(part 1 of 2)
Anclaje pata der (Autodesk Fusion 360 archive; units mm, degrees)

design "Anclaje pata der" references "pilares_anillos_baimax", "Anillos_cuerpo_baimax"
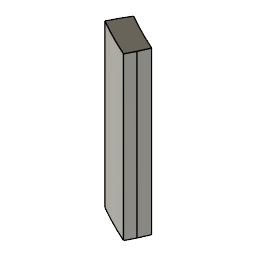
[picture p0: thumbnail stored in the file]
part number: 2026-07-14-14-53-27-253
component_insert "Inserción de componente1"
component_insert "Inserción de componente2"
position "Posición1"
component_insert "Inserción de componente3"
component_insert "Inserción de componente4"
component_insert "Inserción de componente5"
position "Posición2"
sketch "Boceto1" plane through (0, 0, 91.5) normal (0, 0, 1) x axis (1, 0, 0)
  line L1 (1.5, 3) -> (0, 3)
  line L2 (1.5, 0) -> (1.5, 3)
  line L3 (-1.5, 0) -> (1.5, 0)
  line L4 (-1.5, 3) -> (-1.5, 0)
  line L5 (0, 3) -> (-1.5, 3)
  circle C1 centre (0, 1.5) radius 21
  circle C2 centre (0, 1.5) radius 22.75
  circle C3 centre (0, 1.5) radius 5
  point P2 (0, 1.5)
  point P4 (0, 3)
  point P5 (1.5, 3)
  point P6 (1.5, 0)
  point P7 (-1.5, 0)
  point P8 (-1.5, 3)
  concentric C1 C3
  perpendicular L1 L2
  perpendicular L2 L3
  perpendicular L3 L4
  dimension "d1" diameter C3 = 10
  dimension "d2" distance P2 P4 = 1.5
  dimension "d3" distance P4 P5 = 1.5
  dimension "d4" distance P5 P6 = 3
  dimension "d5" distance P6 P7 = 3
  dimension "d6" distance P7 P8 = 3
extrude "Extruir1" new body sketch "Boceto1" profile of L1 L2 L3 L4 L5 along normal blind 7
position "Posición3"
work_plane "PlanoDeObra1" Distance 0
work_plane "PlanoDeObra2" Distance 0
work_plane "PlanoDeObra3" Distance 0
work_plane "PlanoDeObra4" Distance 0
work_plane "PlanoDeObra5" Distance 0
sketch "Boceto2" plane through (-13.1366, 0, 8.8009) normal (-0.8308, 0, 0.5566) x axis (0.5566, 0, 0.8308)
  curve K1 (76.8647, 1.5) -> (74.8126, 1.5)
  curve K2 (75.8387, 7.5) -> (75.8387, -4.5)
  closed curve K3 centre (75.8387, 1.5)
  point P3 (74.8126, 1.5)
  point P4 (76.8647, 1.5)
  point P5 (75.8387, -4.5)
  point P6 (75.8387, 7.5)
  coincident K3 P3
  coincident K3 P4
  coincident K3 P5
  coincident K3 P6
  dimension "d16" = 12
sketch "Boceto3" plane through (-12.068, 0, 51.9927) normal (-0.2261, 0, 0.9741) x axis (0.9741, 0, 0.2261)
  line L1 (52.6699, 3) -> (52.5037, 3)
  line L2 (52.6699, 0) -> (52.5037, 0)
  line L3 (52.6699, 3) -> (52.6699, 0)
  line L4 (53.6699, 1.5) -> (52.6699, 1.5)
  curve K1 (59.1661, 7.4335) -> (59.1661, -4.4335)
  closed curve K2 centre (59.1661, 1.5)
  point P5 (52.6699, 0)
  point P6 (52.6699, 0)
  point P3 (52.6699, 3)
  point P7 (52.6699, 3)
  point P8 (52.6699, 1.5)
  point P11 (59.1661, -4.4335)
  point P12 (59.1661, 7.4335)
  point P9 (53.6699, 1.5)
  coincident P5 P6
  coincident P3 P7
  midpoint L3 P8
  perpendicular L3 L4
  coincident K2 P11
  coincident K2 P12
  dimension "d17" distance P8 P9 = 1
work_plane "PlanoDeObra7" Distance 0
sketch "Boceto4" plane through (37.3705, 0, 0) normal (-1, 0, 0) x axis (0, -1, 0)
  curve K1 (-7.5, 70.5259) -> (4.5, 70.5259)
  curve K2 (-1.5, 67.3726) -> (-1.5, 73.6792)
  closed curve K3 centre (-1.5, 70.5259)
  point P3 (4.5, 70.5259)
  point P4 (-7.5, 70.5259)
  point P5 (-1.5, 73.6792)
  point P6 (-1.5, 67.3726)
  coincident K3 P3
  coincident K3 P4
  coincident K3 P5
  coincident K3 P6
  dimension "d20" distance K3 = 12
sketch "Boceto5" plane through (-0.1048, 0, 0.1825) normal (-0.4982, 0, 0.8671) x axis (0.8671, 0, 0.4982)
  line L1 (53.2165, 0) -> (53.2165, 3)
sketch "Boceto6" plane through (9.9891, 0, -18.2801) normal (-0.4795, 0, 0.8775) x axis (0.8775, 0, 0.4795)
  line L1 (49.7075, 0) -> (49.7075, 3)
  curve K1 (59.1923, 13.5) -> (59.1923, -10.5)
  curve K2 (49.7954, 1.5) -> (68.5892, 1.5)
  closed curve K3 centre (59.1923, 1.5)
  point P5 (59.1923, -10.5)
  point P6 (59.1923, 13.5)
  point P7 (68.5892, 1.5)
  point P8 (49.7954, 1.5)
  coincident K3 P5
  coincident K3 P6
  coincident K3 P7
  coincident K3 P8
  dimension "d36" = 20
sketch "Boceto7" plane through (2.1859, 0, 8.3402) normal (0.2535, 0, 0.9673) x axis (0.9673, 0, -0.2535)
  line L1 (54.1489, 3) -> (54.1489, 0)
  curve K1 (64.3232, 16.5) -> (64.3232, -13.5)
  curve K2 (77.3232, 1.5) -> (51.3232, 1.5)
  closed curve K3 centre (64.3232, 1.5)
  point P5 (64.3232, -13.5)
  point P6 (64.3232, 16.5)
  point P7 (51.3232, 1.5)
  point P8 (77.3232, 1.5)
  coincident K3 P5
  coincident K3 P6
  coincident K3 P7
  coincident K3 P8
  vertical K1
  dimension "d40" distance K3 = 30
  dimension "d41" = 26
work_plane "PlanoDeObra8" Distance 0
sketch "Boceto8" plane through (0, 0, 60.2768) normal (0, 0, 1) x axis (1, 0, 0)
work_plane "PlanoDeObra10" sketch "Boceto4" + "Boceto3"
sketch "Boceto9" plane through (-4.7545, 0, 3.4501) normal (-0.8094, 0, 0.5873) x axis (0, -1, 0)
  curve K1 (-7.5, 80.5735) -> (4.5, 80.5735)
  curve K2 (-1.5, 77.0735) -> (-1.5, 84.0735)
  closed curve K3 centre (-1.5, 80.5735)
  point P3 (4.5, 80.5735)
  point P4 (-7.5, 80.5735)
  point P5 (-1.5, 84.0735)
  point P6 (-1.5, 77.0735)
  coincident K3 P3
  coincident K3 P4
  coincident K3 P5
  coincident K3 P6
  horizontal K1
  dimension "d33" = 7
work_plane "PlanoDeObra12" Distance 0
sketch "Boceto10" plane through (0, 0, 20.5538) normal (0, 0, 1) x axis (1, 0, 0)
  line L1 (64.1747, 1.5) -> (59.5607, 1.5)
  curve K1 (61.8677, 9.5) -> (61.8677, -6.5)
  curve K2 (54.4816, 1.5) -> (69.2538, 1.5)
  closed curve K3 centre (61.8677, 1.5)
  point P5 (61.8677, -6.5)
  point P6 (61.8677, 9.5)
  point P7 (69.2538, 1.5)
  point P8 (54.4816, 1.5)
  point P4 (61.8677, 1.5)
  coincident K3 P5
  coincident K3 P6
  coincident K3 P7
  coincident K3 P8
  midpoint L1 P4
  perpendicular L1 K1
  dimension "d38" distance K3 = 16
  dimension "d39" = 15
work_plane "PlanoDeObra13" Distance 0
sketch "Boceto11" plane through (0, 0, -29.4847) normal (0, 0, 1) x axis (1, 0, 0)
  closed curve K1 centre (63.9334, 1.5)
loft "Solevación1"
work_plane "PlanoDeObra14" AlongDistance 2 ExtraOffset 0
sketch "Boceto12" plane through (52.7171, 0, 38.5545) normal (-0.8072, 0, -0.5903) x axis (-0.5903, 0, 0.8072)
extrude "Extruir2" add of existing geometry blind 2
fillet "Empalme1" radius 1.45
combine "Combinar1"
combine "Combinar2"
sketch "Boceto13" plane through (0, 0, 0) normal (0, 1, 0) x axis (1, 0, 0)
  curve K1 (53.5835, 11.5) -> (53.5662, 8.5)
  line L1 (52.2259, 11.5) -> (53.5835, 11.5)
  line L2 (53.5662, 8.5) -> (52.2037, 8.5)
  curve K2 (53.5662, 8.5) -> (53.5835, 11.5)
  line L3 (52.2037, 8.5) -> (53.5662, 8.5)
  line L4 (53.5835, 11.5) -> (52.2259, 11.5)
  curve K3 (55.2371, 1.5) -> (55.4458, -1.5)
  line L5 (53.8121, 1.5) -> (55.2371, 1.5)
  line L6 (55.4458, -1.5) -> (54.0383, -1.5)
  curve K4 (55.4458, -1.5) -> (55.2371, 1.5)
  line L7 (54.0383, -1.5) -> (55.4458, -1.5)
  line L8 (55.2371, 1.5) -> (53.8121, 1.5)
  curve K5 (36.3076, -71.5) -> (36.2569, -70.5052)
  line L9 (38.0777, -71.5) -> (36.3076, -71.5)
  curve K6 (38.0296, -70.4861) -> (38.0777, -71.5)
  curve K7 (63.9334, 29.4847) -> (38.0296, -70.4861)
  line L10 (54.0473, 29.4847) -> (73.8196, 29.4847)
  curve K8 (63.9334, 29.4847) -> (38.0296, -70.4861)
  curve K9 (38.2035, -68.5) -> (38.0296, -70.4861)
  line L11 (36.4708, -68.5) -> (38.2035, -68.5)
  curve K10 (38.0777, -71.5) -> (38.2035, -68.5)
  line L12 (36.3076, -71.5) -> (38.0777, -71.5)
  line L13 (38.2035, -68.5) -> (36.4708, -68.5)
  line L14 (48.8322, -1.5) -> (55.4458, -1.5)
  line L15 (48.2631, 1.5) -> (55.2371, 1.5)
  line L16 (48.8322, -1.5) -> (48.2631, 1.5)
  line L17 (47.8522, 8.5) -> (53.5662, 8.5)
  line L18 (47.8522, 11.5) -> (47.8522, 8.5)
  line L19 (53.5835, 11.5) -> (47.8522, 11.5)
  line L20 (27.3646, -71.5) -> (38.0777, -71.5)
  line L21 (37.3371, -68.5) -> (37.1927, -71.5)
  line L22 (27.143, -68.5) -> (37.3371, -68.5)
  line L23 (27.143, -68.5) -> (27.3646, -71.5)
  line L24 (54.8106, 1.5) -> (54.7421, -1.5)
  line L25 (54.8106, 1.5) -> (51.7501, 1.5)
  line L26 (48.8322, -1.5) -> (54.7421, -1.5)
  line L27 (48.2631, 1.5) -> (54.8106, 1.5)
  line L28 (52.9047, 11.5) -> (52.885, 8.5)
  line L29 (47.8522, 11.5) -> (52.9047, 11.5)
  line L30 (47.8522, 8.5) -> (52.885, 8.5)
  point P6 (55.4458, -1.5)
  point P19 (55.4458, -1.5)
  point P7 (55.2371, 1.5)
  point P21 (55.2371, 1.5)
  point P2 (53.5662, 8.5)
  point P23 (53.5662, 8.5)
  point P3 (53.5835, 11.5)
  point P26 (53.5835, 11.5)
  point P12 (38.0777, -71.5)
  point P27 (38.0777, -71.5)
  point P29 (37.1927, -71.5)
  point P30 (37.3371, -68.5)
  point P32 (54.7421, -1.5)
  point P33 (54.8106, 1.5)
  point P34 (51.7501, 1.5)
  point P35 (52.885, 8.5)
  point P36 (52.9047, 11.5)
  coincident P6 P19
  parallel L6 L14
  coincident P7 P21
  parallel L5 L15
  coincident P2 P23
  parallel L3 L17
  perpendicular L1 L18
  coincident P3 P26
  perpendicular L18 L19
  coincident P12 P27
  parallel L12 L20
  midpoint L12 P29
  midpoint L11 P30
  parallel L11 L22
  midpoint L7 P32
  coincident L15 P33
  midpoint L15 P34
  midpoint L2 P35
  midpoint L4 P36
extrude "Extruir3" cut sketch "Boceto13" profile of L17 L18 L19 distance 10
extrude "Extruir4" cut sketch "Boceto13" profile of L14 L15 L16 distance 10
extrude "Extruir5" cut sketch "Boceto13" profile of L9 L11 L12 L13 L20 L21 L22 L23 distance 10
copy_paste_bodies "CopiarPegarCuerpos1"
move "Desplazar1"
copy_paste_bodies "CopiarPegarCuerpos2"
move "Desplazar2"
sketch "Boceto14" plane through (0, 0, 68.5) normal (0, 0, 1) x axis (-1, 0, 0)
  curve K1 (-37.3371, 3.0523) -> (-38.2035, 3.2691)
  curve K2 (-38.2035, -6.2691) -> (-37.3371, -6.0523)
  curve K3 (-37.3371, -6.0523) -> (-36.4708, -6.0214)
  curve K4 (-36.4708, -6.0214) -> (-33.2944, -7.0292)
  curve K5 (-32.613, -7.3029) -> (-30.8166, -5.8595)
  line L1 (-30.8166, 2.8595) -> (-30.8166, -5.8595)
  curve K6 (-30.8166, 2.8595) -> (-31.321, 4.0574)
  curve K7 (-31.321, 4.0574) -> (-32.613, 4.3029)
  curve K8 (-33.2944, 4.0292) -> (-36.4708, 3.0214)
  curve K9 (-36.4708, 3.0214) -> (-37.3371, 3.0523)
  line L2 (-36.25, -1.5) -> (-36.75, -1.5)
  line L3 (-33.25, 0.5) -> (-33.25, -1.5)
  line L4 (-33.05, 0.5) -> (-33.25, 0.5)
  line L5 (-36.25, 0.7) -> (-36.25, 0.5)
  line L6 (-36.25, -3.7) -> (-36.25, -3.5)
  line L7 (-33.25, -3.7) -> (-33.25, -3.5)
  line L8 (-33.05, 0.7) -> (-33.05, 0.5)
  line L9 (-33.25, 0.7) -> (-33.05, 0.7)
  line L10 (-36.45, 0.7) -> (-33.25, 0.7)
  line L11 (-36.45, -3.7) -> (-36.45, 0.7)
  line L12 (-33.25, -3.7) -> (-36.45, -3.7)
  line L13 (-33.05, 0.5) -> (-33.05, -3.5)
  line L14 (-33.05, -3.7) -> (-33.25, -3.7)
  line L15 (-33.05, -3.5) -> (-33.05, -3.7)
  arc A1 centre (0, -1.5) radius 38.5 clockwise from (-38.2035, -6.2691) to (-38.2035, 3.2691)
  closed curve K10 centre (-31.321, -1.5)
  closed curve K11 centre (-31.321, -1.5)
  circle C1 centre (0, -1.5) radius 36.75
  circle C2 centre (0, -1.5) radius 36.75
  point P18 (-36.75, -1.5)
  point P19 (-36.25, -1.5)
  point P20 (-33.25, -1.5)
  point P21 (-36.25, 0.5)
  point P22 (-33.25, 0.5)
  point P23 (-36.25, -3.5)
  point P24 (-33.25, -3.5)
  point P25 (-33.05, 0.5)
  point P26 (-33.25, 0.7)
  point P27 (-36.25, 0.7)
  point P28 (-36.25, -3.7)
  point P29 (-33.25, -3.7)
  point P30 (-33.05, -3.5)
  point P31 (-33.05, 0.7)
  point P32 (-36.45, 0.7)
  point P33 (-36.45, -3.7)
  coincident C2 P18
  perpendicular L1 L2
  perpendicular L3 L4
  perpendicular L4 L8
  perpendicular L5 L10
  perpendicular L7 L14
  dimension "d56" distance P18 P19 = 0.5
  dimension "d57" distance P19 P20 = 3
  dimension "d58" distance P19 P21 = 2
  dimension "d59" distance P21 P22 = 3
  dimension "d61" distance P19 P23 = 2
  dimension "d62" distance P22 P24 = 4
  dimension "d63" distance P22 P25 = 0.2
  dimension "d64" distance P22 P26 = 0.2
  dimension "d65" distance P21 P27 = 0.2
  dimension "d68" distance P23 P28 = 0.2
  dimension "d69" distance P24 P29 = 0.2
  dimension "d70" distance P24 P30 = 0.2
  dimension "d71" distance P25 P31 = 0.2
  dimension "d72" distance P26 P32 = 3.2
  dimension "d73" distance P32 P33 = 4.4
extrude "Extruir6" cut sketch "Boceto14" profile of L8 L9 L10 L11 L12 L13 L14 L15 distance 40
extrude "Extruir7" cut of existing geometry blind -0.2
extrude "Extruir8" cut of existing geometry blind -0.2
extrude "Extruir9" cut of existing geometry blind -0.2
extrude "Extruir10" cut of existing geometry blind -0.2
extrude "Extruir11" cut of existing geometry blind -0.2
extrude "Extruir12" cut of existing geometry blind -0.2
sketch "Boceto15" plane through (0, 0, 0) normal (0, 1, 0) x axis (1, 0, 0)
  curve K1 (53.5835, 11.5) -> (53.586, 11.7)
  curve K2 (53.5662, 8.5) -> (53.5835, 11.5)
  curve K3 (53.5665, 8.3) -> (53.5662, 8.5)
  line L1 (52.4857, 8.3) -> (53.5665, 8.3)
  curve K4 (52.8572, 8.5) -> (52.4857, 8.3)
  line L2 (52.2037, 8.5) -> (52.8572, 8.5)
  line L3 (51.3074, 8.5) -> (52.2037, 8.5)
  line L4 (52.8572, 8.5) -> (52.2037, 8.5)
  curve K5 (52.4857, 8.3) -> (52.8572, 8.5)
  line L5 (53.5665, 8.3) -> (52.4857, 8.3)
  curve K6 (53.5662, 8.5) -> (53.5665, 8.3)
  curve K7 (53.5835, 11.5) -> (53.5662, 8.5)
  curve K8 (53.586, 11.7) -> (53.5835, 11.5)
  line L6 (51.416, 11.7) -> (53.586, 11.7)
  line L7 (30.954, -71.7) -> (38.0987, -71.7)
  line L8 (30.954, -71.7) -> (30.8357, -71.8618)
  line L9 (38.0987, -71.7) -> (30.954, -71.7)
  curve K9 (38.0777, -71.5) -> (38.0987, -71.7)
  curve K10 (38.0296, -70.4861) -> (38.0777, -71.5)
  curve K11 (63.9334, 29.4847) -> (38.0296, -70.4861)
  line L10 (54.0473, 29.4847) -> (73.8196, 29.4847)
  curve K12 (63.9334, 29.4847) -> (38.0296, -70.4861)
  curve K13 (38.2035, -68.5) -> (38.0296, -70.4861)
  curve K14 (38.2386, -68.3) -> (38.2035, -68.5)
  line L11 (33.4406, -68.3) -> (38.2386, -68.3)
  line L12 (34.2543, -67.1874) -> (33.4406, -68.3)
  curve K15 (36.45, -67.6695) -> (34.2543, -67.1874)
  line L13 (36.45, -67.4592) -> (36.45, -67.6695)
  curve K16 (34.2543, -67.1874) -> (36.45, -67.6695)
  line L14 (34.2543, -67.1874) -> (33.4406, -68.3)
  line L15 (38.2386, -68.3) -> (33.4406, -68.3)
  curve K17 (38.2035, -68.5) -> (38.2386, -68.3)
  curve K18 (38.0777, -71.5) -> (38.2035, -68.5)
  curve K19 (38.0987, -71.7) -> (38.0777, -71.5)
  curve K20 (36.45, -73.4124) -> (33.05, -72.6307)
  line L16 (36.45, -73.6296) -> (36.45, -73.4124)
  curve K21 (33.05, -72.6307) -> (36.45, -73.4124)
  line L17 (33.05, -72.8531) -> (33.05, -72.6307)
  curve K22 (55.4588, -1.7) -> (55.4458, -1.5)
  line L18 (53.3559, -1.7) -> (55.4588, -1.7)
  curve K23 (55.4458, -1.5) -> (55.4588, -1.7)
  curve K24 (55.2371, 1.5) -> (55.4458, -1.5)
  line L19 (54.8106, 1.5) -> (55.2371, 1.5)
  line L20 (53.8121, 1.5) -> (54.8106, 1.5)
  line L21 (52.2582, 1.5) -> (53.8121, 1.5)
  line L22 (54.734, 1.5) -> (53.8121, 1.5)
  line L23 (55.2371, 1.5) -> (54.734, 1.5)
  curve K25 (55.4458, -1.5) -> (55.2371, 1.5)
  line L24 (55.2371, 1.5) -> (55.4588, -1.7)
  line L25 (55.2715, 0.9996) -> (55.2371, 1.5)
  line L26 (55.2233, 1.7) -> (55.2371, 1.7)
  line L27 (55.2233, 1.7) -> (55.2371, 1.5)
  line L28 (51.3186, 1.7) -> (55.2233, 1.7)
  line L29 (51.3186, 1.4033) -> (51.3186, 1.7)
  line L30 (51.3186, 1.4033) -> (52.2582, 1.5)
  line L31 (50.5573, 8.3) -> (53.5665, 8.3)
  line L32 (50.5573, 9.2223) -> (50.5573, 8.3)
  line L33 (53.5665, 8.3) -> (50.5573, 9.2223)
  point P30 (55.4588, -1.7)
  point P37 (55.4588, -1.7)
  point P32 (55.2371, 1.5)
  point P38 (55.2371, 1.5)
  point P40 (55.2715, 0.9996)
  point P42 (55.2371, 1.5)
  point P35 (52.2582, 1.5)
  point P45 (52.2582, 1.5)
  point P5 (53.5665, 8.3)
  point P46 (53.5665, 8.3)
  point P49 (53.5665, 8.3)
  point P39 (55.2371, 1.7)
  coincident P30 P37
  coincident P32 P38
  coincident K24 P40
  coincident K25 P40
  coincident P32 P42
  parallel L26 L28
  perpendicular L28 L29
  coincident P35 P45
  coincident P5 P46
  parallel L1 L31
  perpendicular L31 L32
  coincident P5 P49
  dimension "d88" distance P38 P39 = 0.2
extrude "Extruir13" cut sketch "Boceto15" profile of L19 L20 L21 L22 L23 L27 L28 L29 L30 distance 120
extrude "Extruir14" cut of existing geometry to an object
extrude "Extruir15" cut of existing geometry to an object
extrude "Extruir16" cut sketch "Boceto15" profile of L1 L5 L31 L32 L33 distance 120
extrude "Extruir17" new body of existing geometry blind 3.2
extrude "Extruir18" cut of existing geometry blind -0.2
extrude "Extruir19" cut of existing geometry blind -4
extrude "Extruir20" cut of existing geometry blind -0.2
extrude "Extruir21" cut of existing geometry blind -0.2
extrude "Extruir22" cut of existing geometry blind -4
extrude "Extruir23" add of existing geometry blind 6
move "Desplazar3"
extrude "Extruir24" add of existing geometry blind 2
sketch "Boceto16" plane through (36.25, 0, 0) normal (1, 0, 0) x axis (0, 1, 0)
  line L1 (3.5, 74.9512) -> (3.5, 65.2)
  curve K1 (3.5, 74.9512) -> (-0.5, 74.9512)
  line L2 (-0.5, 65.2) -> (-0.5, 74.9512)
  line L3 (3.5, 65.2) -> (-0.5, 65.2)
  line L4 (-0.5, 73.9512) -> (-0.5, 74.9512)
  line L5 (3.5, 73.9512) -> (-0.5, 73.9512)
  point P4 (-0.5, 74.9512)
  point P6 (-0.5, 74.9512)
  point P8 (3.5, 73.9512)
  point P7 (-0.5, 73.9512)
  coincident P4 P6
  parallel L2 L4
  coincident L1 P8
  perpendicular L1 L5
  dimension "d113" distance P6 P7 = 1
extrude "Extruir25" add sketch "Boceto16" profile of L1 K1 L2 L4 L5 along normal blind 1
extrude "Extruir26" cut of existing geometry blind -0.5
extrude "Extruir27" add of existing geometry blind 0.3
copy_paste_bodies "CopiarPegarCuerpos3"
move "Desplazar4"
work_plane "PlanoDeObra15" AlongDistance 0 ExtraOffset 0
sketch "Boceto17" plane through (0, 0, -38.5) normal (0, 0, -1) x axis (-1, 0, 0)
offset_faces "CarasDesfase1" distance 5
fillet "Empalme2" radius 7
work_plane "PlanoDeObra16" sketch "Boceto17" AlongDistance -3 ExtraOffset 0
sketch "Boceto18" plane through (0, 0, -35.5) normal (0, 0, -1) x axis (-1, 0, 0)
  curve K1 (-50.3733, 42.62) -> (-50.6427, 42.9873)
  curve K2 (-50.6427, 42.9873) -> (-50.3733, 42.62)
  curve K3 (-45.3276, 46.9224) -> (-45.3276, 46.9224)
  circle C1 centre (-48.3943, 40.8173) radius 1.75
  circle C2 centre (-51.1986, 51.5115) radius 1.75
  circle C3 centre (-47.4332, 56.089) radius 1.75
  circle C4 centre (-42.4948, 59.6646) radius 1.75
  circle C5 centre (-36.1301, 60.3304) radius 1.75
  point P6 (-48.3943, 40.8173)
  point P7 (-51.1986, 51.5115)
  point P8 (-47.4332, 56.089)
  point P9 (-42.4948, 59.6646)
  point P10 (-36.1301, 60.3304)
  coincident K2 P6
  coincident K2 P7
  coincident K2 P8
  coincident K2 P9
  coincident K2 P10
  dimension "d127" diameter C1 = 3.5
  dimension "d128" diameter C2 = 3.5
  dimension "d129" diameter C3 = 3.5
  dimension "d130" diameter C4 = 3.5
  dimension "d131" diameter C5 = 3.5
work_plane "PlanoDeObra17" sketch "Boceto18" AlongDistance -4 ExtraOffset 0
sketch "Boceto19" plane through (0, 0, -31.5) normal (0, 0, -1) x axis (-1, 0, 0)
  line L1 (-45.3276, 46.9224) -> (-50.6427, 42.9873)
  curve K1 (-50.3733, 42.62) -> (-50.6427, 42.9873)
  curve K2 (-50.6427, 42.9873) -> (-50.3733, 42.62)
  line L2 (-45.3276, 46.9224) -> (-50.6427, 42.9873)
  curve K3 (-45.3276, 46.9224) -> (-45.3276, 46.9224)
  circle C1 centre (-47.2256, 42.1199) radius 2
  circle C2 centre (-49.6515, 50.6936) radius 2
  circle C3 centre (-46.2588, 54.7916) radius 2
  circle C4 centre (-41.7932, 58.0614) radius 2
  circle C5 centre (-36.7005, 58.676) radius 2
  dimension "d134" diameter C1 = 4
  dimension "d135" diameter C2 = 4
  dimension "d136" diameter C3 = 4
  dimension "d137" diameter C4 = 4
  dimension "d138" diameter C5 = 4
loft "Solevación2" sketch "Boceto19" + "Boceto18"
loft "Solevación3" sketch "Boceto18" + "Boceto19"
loft "Solevación4" sketch "Boceto18" + "Boceto19"
loft "Solevación5" sketch "Boceto18" + "Boceto19"
loft "Solevación6" sketch "Boceto18" + "Boceto19"
fillet "Empalme3" radius 1
fillet "Empalme4" radius 1
fillet "Empalme5" radius 1
fillet "Empalme6" radius 1
fillet "Empalme7" radius 1
extrude "Extruir28" add of existing geometry blind 3
extrude "Extruir29" add of existing geometry blind 3
extrude "Extruir30" add of existing geometry blind 3
extrude "Extruir31" add of existing geometry blind 3
copy_paste_bodies "CopiarPegarCuerpos4"
move "Desplazar5"
mirror "Simetría1" mirrorStitchTolerance 0.1
work_plane "PlanoDeObra18" AlongDistance 0 ExtraOffset 0
sketch "Boceto20" plane through (0, -52.25, 0) normal (0, -1, 0) x axis (0, 0, 1)
  line L1 (-21.5, 0) -> (-18.5, 0)
  line L2 (-20, -25) -> (-20, 0)
  line L3 (-20, 25) -> (-20, -25)
  circle C1 centre (-20, -25) radius 12.5
  circle C2 centre (-20, 25) radius 12.5
  point P4 (-20, 0)
  point P5 (-20, -25)
  point P7 (-20, -25)
  point P6 (-20, 25)
  point P8 (-20, 25)
  midpoint L1 P4
  perpendicular L1 L2
  perpendicular L1 L3
  coincident P5 P7
  coincident P6 P8
  dimension "d161" distance P4 P5 = 25
  dimension "d162" distance P5 P6 = 50
  dimension "d163" diameter C1 = 25
  dimension "d164" diameter C2 = 25
extrude "Extruir32" new body sketch "Boceto20" profile of C1 C2 along normal blind 25
move "Desplazar6"
extrude "Extruir33" add of existing geometry blind 25
combine "Combinar3"
combine "Combinar4"
move "Desplazar7"
sketch "Boceto21" plane through (0, 0, 0) normal (1, 0, 0) x axis (0, 1, 0)
  curve K1 (-72.9701, -18.5) -> (-74.0431, -21.5)
  line L1 (-70.3375, -18.5) -> (-72.9701, -18.5)
  curve K2 (-71.4962, -21.5) -> (-70.3375, -18.5)
  line L2 (-74.0431, -21.5) -> (-71.4962, -21.5)
  curve K3 (-87.3448, -21.5) -> (-87.6216, -18.5)
  line L3 (-85.5239, -21.5) -> (-87.3448, -21.5)
  curve K4 (-85.8114, -18.5) -> (-85.5239, -21.5)
  line L4 (-87.6216, -18.5) -> (-85.8114, -18.5)
  curve K5 (-91.0848, -11.5) -> (-90.635, -8.5)
  line L5 (-89.2774, -11.5) -> (-91.0848, -11.5)
  curve K6 (-88.8115, -8.5) -> (-89.2774, -11.5)
  line L6 (-90.635, -8.5) -> (-88.8115, -8.5)
  curve K7 (-79.9495, -8.5) -> (-78.4871, -11.5)
  line L7 (-77.6312, -8.5) -> (-79.9495, -8.5)
  curve K8 (-76.0786, -11.5) -> (-77.6312, -8.5)
  line L8 (-78.4871, -11.5) -> (-76.0786, -11.5)
  line L9 (-67.25, -3.5) -> (-67.25, -28.5)
  line L10 (-117.25, -28.5) -> (-117.25, -3.5)
  line L11 (-67.25, -8.5) -> (-77.6312, -8.5)
  line L12 (-67.25, -11.5) -> (-76.0786, -11.5)
  line L13 (-67.25, -18.5) -> (-70.3375, -18.5)
  line L14 (-67.25, -21.5) -> (-71.4962, -21.5)
  point P16 (-77.6312, -8.5)
  point P22 (-77.6312, -8.5)
  point P23 (-67.25, -8.5)
  point P17 (-76.0786, -11.5)
  point P24 (-76.0786, -11.5)
  point P25 (-67.25, -11.5)
  point P4 (-70.3375, -18.5)
  point P26 (-70.3375, -18.5)
  point P27 (-67.25, -18.5)
  point P5 (-71.4962, -21.5)
  point P28 (-71.4962, -21.5)
  point P29 (-67.25, -21.5)
  coincident P16 P22
  coincident L9 P23
  perpendicular L9 L11
  coincident P17 P24
  coincident L9 P25
  perpendicular L9 L12
  coincident P4 P26
  coincident L9 P27
  perpendicular L9 L13
  coincident P5 P28
  coincident L9 P29
  perpendicular L9 L14
extrude "Extruir34" cut sketch "Boceto21" profile of K1 L1 K2 L2 K7 L7 K8 L8 L9 L11 L12 L13 L14 along normal blind 100
sketch "Boceto22" plane through (0, 0, -21.5) normal (0, 0, 1) x axis (-1, 0, 0)
  line L1 (-13.775, 87.3448) -> (-13.775, 85.5239)
  line L2 (-36.225, 71.4962) -> (-36.225, 74.0431)
  line L3 (-13.775, 71.4962) -> (-36.225, 71.4962)
  line L4 (-13.775, 74.0431) -> (-13.775, 71.4962)
  line L5 (-33.7296, 74.0431) -> (-13.775, 74.0431)
  line L6 (-13.775, 85.5239) -> (-13.775, 74.0431)
  arc A1 centre (0, 38.5) radius 49 clockwise from (-33.7296, 74.0431) to (-13.775, 85.5239)
  arc A2 centre (0, 38.5) radius 50.75 clockwise from (-36.225, 74.0431) to (-13.775, 87.3448)
  point P9 (-13.775, 74.0431)
  point P10 (-13.775, 74.0431)
  point P2 (-13.775, 85.5239)
  point P11 (-13.775, 85.5239)
  coincident P9 P10
  coincident P2 P11
extrude "Extruir35" cut sketch "Boceto22" profile of A1 L5 L6 to an object
extrude "Extruir36" cut of existing geometry blind -6
extrude "Extruir37" cut of existing geometry blind -1
extrude "Extruir38" cut of existing geometry blind -3
extrude "Extruir39" cut of existing geometry blind -1
extrude "Extruir40" cut of existing geometry blind -1
extrude "Extruir41" cut of existing geometry blind -3
sketch "Boceto23" plane through (0, 0, -11.5) normal (0, 0, 1) x axis (-1, 0, 0)
  line L1 (-13.3381, 91.0848) -> (-13.3381, 89.2774)
  line L2 (-36.6619, 76.0786) -> (-36.6619, 78.4871)
  line L3 (-13.3381, 76.0786) -> (-36.6619, 76.0786)
  line L4 (-13.3381, 78.4871) -> (-13.3381, 76.0786)
  line L5 (-34.0189, 78.4871) -> (-13.3381, 78.4871)
  line L6 (-13.3381, 78.4871) -> (-13.3381, 89.2774)
  arc A1 centre (0, 38.5) radius 52.5 clockwise from (-34.0189, 78.4871) to (-13.3381, 89.2774)
  arc A2 centre (0, 38.5) radius 54.25 clockwise from (-36.6619, 78.4871) to (-13.3381, 91.0848)
  point P2 (-13.3381, 89.2774)
  point P10 (-13.3381, 89.2774)
  point P9 (-13.3381, 78.4871)
  point P11 (-13.3381, 78.4871)
  coincident P2 P10
  coincident P9 P11
extrude "Extruir42" cut sketch "Boceto23" profile of A1 L5 L6 to an object
extrude "Extruir43" cut of existing geometry blind -0.2
extrude "Extruir44" cut of existing geometry blind -0.2
extrude "Extruir45" cut of existing geometry blind -0.2
extrude "Extruir46" cut of existing geometry blind -0.2
extrude "Extruir47" cut of existing geometry blind -3
extrude "Extruir48" cut of existing geometry blind -3
extrude "Extruir49" cut of existing geometry blind -4
extrude "Extruir50" cut of existing geometry blind -4
extrude "Extruir51" cut of existing geometry blind -0.2
extrude "Extruir52" cut of existing geometry blind -0.2
extrude "Extruir53" cut of existing geometry blind -0.2
extrude "Extruir54" cut of existing geometry blind -0.2
extrude "Extruir55" cut of existing geometry blind -3
extrude "Extruir56" cut of existing geometry blind -3
extrude "Extruir57" cut of existing geometry blind -3
extrude "Extruir58" cut of existing geometry blind -3
move "Desplazar8"
extrude "Extruir59" cut of existing geometry blind -10
fillet "Empalme8" radius 4
sketch "Boceto24" plane through (0, 0, -31.5) normal (0, 0, -1) x axis (-1, 0, 0)
  circle C1 centre (0, 1.5) radius 45.5
  circle C2 centre (0, 1.5) radius 47.25
sketch "Boceto25" plane through (0, 0, 0) normal (0, 0, 1) x axis (1, 0, 0)
  line L1 (12.7134, -30.3375) -> (12.7134, -27.25)
  line L2 (12.7134, -47.6216) -> (12.7134, -30.3375)
  line L3 (12.7526, -47.6216) -> (12.7134, -47.6216)
  curve K1 (13.775, -47.3448) -> (12.7526, -47.6216)
  curve K2 (13.8753, -47.3164) -> (13.775, -47.3448)
  line L4 (13.8753, -31.4962) -> (13.8753, -47.3164)
  line L5 (13.8753, -27.25) -> (13.8753, -31.4962)
  line L6 (36.1247, -31.4962) -> (36.1247, -27.25)
  line L7 (36.1247, -34.145) -> (36.1247, -31.4962)
  curve K3 (36.225, -34.0431) -> (36.1247, -34.145)
  curve K4 (37.2474, -32.9701) -> (36.225, -34.0431)
  line L8 (37.2866, -32.9701) -> (37.2474, -32.9701)
  line L9 (37.2866, -30.3375) -> (37.2866, -32.9701)
  line L10 (37.2866, -27.25) -> (37.2866, -30.3375)
  line L11 (36.7371, -36.0786) -> (36.7371, -27.25)
  line L12 (36.7371, -38.4871) -> (36.7371, -36.0786)
  line L13 (36.7371, -38.4871) -> (36.6619, -38.4871)
  curve K5 (35, -39.9495) -> (36.6619, -38.4871)
  curve K6 (34.8468, -40.0784) -> (35, -39.9495)
  line L14 (34.8468, -37.6312) -> (34.8468, -40.0784)
  line L15 (34.8468, -27.25) -> (34.8468, -37.6312)
  line L16 (15.1532, -37.6312) -> (15.1532, -27.25)
  line L17 (15.1532, -50.5907) -> (15.1532, -37.6312)
  curve K7 (15, -50.635) -> (15.1532, -50.5907)
  curve K8 (13.3381, -51.0848) -> (15, -50.635)
  line L18 (13.3381, -51.0848) -> (13.2629, -51.0848)
  line L19 (13.2629, -36.0786) -> (13.2629, -51.0848)
  line L20 (13.2629, -27.25) -> (13.2629, -36.0786)
  line L21 (37.5, -63.25) -> (12.5, -63.25)
  line L22 (27.9005, -27.25) -> (12.7134, -27.25)
  circle C1 centre (0, 1.5) radius 45.5
  circle C2 centre (0, 1.5) radius 47.25
  circle C3 centre (0, 0) radius 39
  point P1 (0, 0)
  point P37 (0, 0)
  point P2 (12.7134, -27.25)
  point P38 (12.7134, -27.25)
  point P39 (27.9005, -27.25)
  coincident P1 P37
  coincident P2 P38
  coincident C3 P39
  perpendicular L16 L22
  dimension "d223" diameter C3 = 78
extrude "Extruir60" cut sketch "Boceto25" profile of L1 L2 L4 L5 L16 L19 L20 C3 L22 against normal blind 200
extrude "Extruir61" cut of existing geometry blind -3
sketch "Boceto26" plane through (0, 0, -21.7) normal (0, 0, 1) x axis (-1, 0, 0)
  line L1 (-13.8753, 47.3164) -> (-13.8753, 36.4483)
  line L2 (-36.1247, 31.4962) -> (-36.1247, 34.145)
  line L3 (-22.9997, 31.4962) -> (-36.1247, 31.4962)
  line L4 (-36.1247, 31.4962) -> (-22.9997, 31.4962)
  line L5 (-36.1247, 27.25) -> (-36.1247, 31.4962)
  line L6 (-27.9005, 27.25) -> (-36.1247, 27.25)
  arc A1 centre (0, 0) radius 39 clockwise from (-22.9997, 31.4962) to (-13.8753, 36.4483)
  arc A2 centre (0, -1.5) radius 50.75 clockwise from (-36.1247, 34.145) to (-13.8753, 47.3164)
  arc A3 centre (0, 0) radius 39 clockwise from (-27.9005, 27.25) to (-22.9997, 31.4962)
extrude "Extruir62" cut of existing geometry blind -10
extrude "Extruir63" cut of existing geometry blind -10
sketch "Boceto27" plane through (0, 0, -18.3) normal (0, 0, -1) x axis (1, 0, 0)
  line L1 (37.2866, 30.3375) -> (24.5079, 30.3375)
  line L2 (37.2866, 32.9701) -> (37.2866, 30.3375)
  line L3 (37.2474, 32.9701) -> (37.2866, 32.9701)
  line L4 (12.7134, 47.6216) -> (12.7526, 47.6216)
  line L5 (12.7134, 36.8696) -> (12.7134, 47.6216)
  curve K1 (12.7134, 36.8696) -> (13.2629, 36.6756)
  line L6 (36.7371, 27.25) -> (27.9005, 27.25)
  line L7 (27.9005, 27.25) -> (37.2866, 27.25)
  arc A1 centre (0, 0) radius 39 clockwise from (12.7134, 36.8696) to (24.5079, 30.3375)
  arc A2 centre (0, -1.5) radius 50.75 clockwise from (12.7526, 47.6216) to (37.2474, 32.9701)
  circle C1 centre (0, 0) radius 42.5
  arc A3 centre (0, 0) radius 39 clockwise from (12.7134, 36.8696) to (24.5079, 30.3375)
  arc A4 centre (0, 0) radius 39 clockwise from (13.2629, 36.6756) to (14.8098, 36.0786)
  arc A5 centre (0, 0) radius 39 clockwise from (14.8098, 36.0786) to (27.9005, 27.25)
  arc A6 centre (0, 0) radius 39 clockwise from (24.5079, 30.3375) to (27.9005, 27.25)
  point P1 (0, 0)
  point P11 (0, 0)
  coincident P1 P11
  dimension "d232" diameter C1 = 85
extrude "Extruir64" cut sketch "Boceto27" profile of A1 L1 L5 C1 A3 K1 A4 A5 A6 L6 L7 against normal blind 50
extrude "Extruir65" cut of existing geometry blind -3
sketch "Boceto28" plane through (0, 0, -11.7) normal (0, 0, 1) x axis (-1, 0, 0)
  line L1 (-13.2629, 51.0848) -> (-13.2629, 40.3775)
  line L2 (-13.3381, 51.0848) -> (-13.2629, 51.0848)
  line L3 (-36.7371, 38.4871) -> (-36.6619, 38.4871)
  line L4 (-36.7371, 36.0786) -> (-36.7371, 38.4871)
  line L5 (-22.4629, 36.0786) -> (-36.7371, 36.0786)
  line L6 (0, -1.5) -> (-23.7925, 45.2992)
  line L7 (-23.6566, 45.0318) -> (-23.7925, 45.2992)
  line L8 (-22.1157, 42.001) -> (-23.6566, 45.0318)
  line L9 (-20.2119, 44.8759) -> (-22.8862, 43.5164)
  line L10 (-25.5604, 42.1568) -> (-20.2119, 44.8759)
  line L11 (-20.2119, 44.8759) -> (0, -1.5)
  line L12 (-20.9432, 46.3144) -> (-20.2119, 44.8759)
  line L13 (0, -1.5) -> (-25.5604, 42.1568)
  line L14 (-26.2917, 43.5953) -> (-25.5604, 42.1568)
  curve K1 (-12.7134, 40.5539) -> (-13.2629, 40.3775)
  line L15 (-36.7371, 27.25) -> (-32.6142, 27.25)
  line L16 (-32.6142, 27.25) -> (-37.2866, 27.25)
  arc A1 centre (0, 0) radius 42.5 clockwise from (-22.4629, 36.0786) to (-13.2629, 40.3775)
  arc A2 centre (0, -1.5) radius 54.25 clockwise from (-36.6619, 38.4871) to (-13.3381, 51.0848)
  circle C1 centre (0, -1.5) radius 52.5
  circle C2 centre (0, -1.5) radius 52.5
  circle C3 centre (0, -1.5) radius 52.5
  circle C4 centre (0, -1.5) radius 48.8
  circle C5 centre (0, -1.5) radius 52.2
  circle C6 centre (0, -1.5) radius 47
  arc A3 centre (0, 0) radius 42.5 clockwise from (-22.4629, 36.0786) to (-13.2629, 40.3775)
  arc A4 centre (0, 0) radius 42.5 clockwise from (-32.6142, 27.25) to (-22.4629, 36.0786)
  arc A5 centre (0, 0) radius 42.5 clockwise from (-32.6142, 27.25) to (-29.7638, 30.3375)
  arc A6 centre (0, 0) radius 42.5 clockwise from (-29.7638, 30.3375) to (-12.7134, 40.5539)
  point P13 (-23.7925, 45.2992)
  point P12 (0, -1.5)
  point P14 (0, -1.5)
  point P16 (-22.1157, 42.001)
  point P18 (0, -1.5)
  point P15 (-23.6566, 45.0318)
  point P19 (-22.8862, 43.5164)
  point P22 (-20.9432, 46.3144)
  point P23 (-26.2917, 43.5953)
  point P20 (-20.2119, 44.8759)
  point P21 (-25.5604, 42.1568)
  coincident C3 P13
  coincident P12 P14
  parallel L6 L7
  parallel L6 L8
  concentric C1 C4
  coincident P16 C4
  coincident P14 P18
  coincident P15 C5
  midpoint L8 P19
  perpendicular L8 L9
  parallel L9 L10
  coincident C5 P22
  perpendicular L9 L12
  coincident C5 P23
  perpendicular L10 L14
  concentric C1 C6
  dimension "d237" distance P13 P15 = 0.3
  dimension "d238" distance P15 P16 = 3.4
  dimension "d239" distance P19 P20 = 3
  dimension "d240" distance P20 P21 = 6
  dimension "d243" diameter C6 = 94
extrude "Extruir66" cut sketch "Boceto28" profile of L6 L8 C4 C5 L9 L10 L11 L12 L13 L14 distance -10
sketch "Boceto29" plane through (0, -27.25, 0) normal (0, 1, 0) x axis (-1, 0, 0)
  line L1 (-32.6142, -11.7) -> (-32.6142, -18.3)
  line L2 (-36.7371, -11.7) -> (-32.6142, -11.7)
  line L3 (-32.6142, -18.3) -> (-37.2866, -18.3)
  arc A1 centre (-25, -16) radius 12.5 clockwise from (-37.2866, -18.3) to (-36.7371, -11.7)
extrude "Extruir67" cut sketch "Boceto28" profile of A1 L1 L5 L6 L11 L13 C6 A3 A4 A5 A6 L15 L16 distance -10
extrude "Extruir68" cut of existing geometry blind -3
sketch "Boceto30" plane through (0, 0, -11.7) normal (0, 0, 1) x axis (-1, 0, 0)
  line L1 (-13.2629, 51.0848) -> (-13.2629, 43.5899)
  line L2 (-13.3381, 51.0848) -> (-13.2629, 51.0848)
  line L3 (-36.7371, 38.4871) -> (-36.6619, 38.4871)
  line L4 (-36.7371, 36.0786) -> (-36.7371, 38.4871)
  line L5 (-28.2284, 36.0786) -> (-36.7371, 36.0786)
  line L6 (-20.2119, 44.8759) -> (-20.9432, 46.3144)
  line L7 (-19.4971, 43.2359) -> (-20.2119, 44.8759)
  line L8 (-25.5604, 42.1568) -> (-24.6565, 40.6129)
  line L9 (-26.2917, 43.5953) -> (-25.5604, 42.1568)
  arc A1 centre (0, -1.5) radius 47 clockwise from (-28.2284, 36.0786) to (-13.2629, 43.5899)
  arc A2 centre (0, -1.5) radius 54.25 clockwise from (-36.6619, 38.4871) to (-13.3381, 51.0848)
  arc A3 centre (0, -1.5) radius 48.8 clockwise from (-24.6565, 40.6129) to (-19.4971, 43.2359)
  arc A4 centre (0, -1.5) radius 52.2 clockwise from (-26.2917, 43.5953) to (-20.9432, 46.3144)
extrude "Extruir69" new body sketch "Boceto30" profile of L6 L7 A3 L8 L9 A4 along normal blind 10
offset_faces "CarasDesfase2" distance -0.4
extrude "Extruir70" add of existing geometry blind 9.8
mirror "Simetría2" mirrorStitchTolerance 0.1
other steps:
base_feature "Elemento base1"
base_feature "Elemento base2"
base_feature "Elemento base3"
base_feature "Elemento base4"

design "Anillos_cuerpo_baimax"
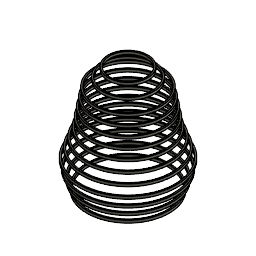
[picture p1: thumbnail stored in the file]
part number: 2026-07-06-18-36-34-739
parameter "d_1" = 112
parameter "d_1_int" = 108.5 (= "d_1 - 3.5 mm")
parameter "h_1" = -10
parameter "d_2" = 108.5
parameter "d_2_int" = 105 (= "d_2 - 3.5 mm")
parameter "h_2" = 10
parameter "h_3" = -20
parameter "h_4" = 20
parameter "h_5" = -30
parameter "h_6" = 30
parameter "h_7" = 40
parameter "d_3" = 105 (= "d_2_int")
parameter "d_3_int" = 101.5 (= "d_3 - 3.5 mm")
parameter "d_4" = 101.5 (= "d_3_int")
parameter "d_4_int" = 98 (= "d_4 - 3.5 mm")
parameter "d_5" = 98 (= "d_4_int")
parameter "d_5_int" = 94.5 (= "d_5 - 3.5 mm")
parameter "d_6" = 94.5 (= "d_5_int")
parameter "d_6_int" = 91 (= "d_6 - 3.5 mm")
parameter "d_7" = 91 (= "d_6_int")
parameter "d_7_int" = 87.5 (= "d_7 - 3.5 mm")
parameter "d_8" = 87.5 (= "d_7_int")
parameter "d_8_int" = 84 (= "d_8 - 3.5 mm")
parameter "h_8" = 50
parameter "h_9" = 60
parameter "h_10" = 70
parameter "h_11" = 110
parameter "h_12" = 120
parameter "h_13" = 130
parameter "h_14" = 140
parameter "h_15" = 80
parameter "d_9" = 84 (= "d_8_int")
parameter "d_9_int" = 80.5 (= "d_9 - 3.5 mm")
parameter "d_10" = 80.5 (= "d_9_int")
parameter "d_10_int" = 77 (= "d_10 - 3.5 mm")
parameter "d_11" = 77 (= "d_10_int")
parameter "d_11_int" = 73.5 (= "d_11 - 3.5 mm")
parameter "d_12" = 73.5 (= "d_11_int")
parameter "d_12_int" = 70 (= "d_12 - 3.5 mm")
parameter "d_13" = 70 (= "d_12_int")
parameter "d_13_int" = 66.5 (= "d_13 - 3.5 mm")
parameter "d_14" = 66.5 (= "d_13_int")
parameter "d_14_int" = 63 (= "d_14 - 3.5 mm")
parameter "d_15" = 63 (= "d_14_int")
parameter "d_15_int" = 59.5 (= "d_15 - 3.5 mm")
parameter "d_16" = 59.5 (= "d_15_int")
parameter "d_16_int" = 56 (= "d_16 - 3.5 mm")
parameter "h_16" = 160
parameter "h_17" = 170
parameter "h_18" = 180
parameter "h_19" = 90
parameter "h_20" = 200
parameter "d_17" = 56 (= "d_16_int")
parameter "d_17_int" = 52.5 (= "d_17 - 3.5 mm")
parameter "d_18" = 52.5 (= "d_17_int")
parameter "d_18_int" = 49 (= "d_18 - 3.5 mm")
parameter "d_19" = 49 (= "d_18_int")
parameter "d_19_int" = 45.5 (= "d_19 - 3.5 mm")
parameter "d_20" = 45.5 (= "d_19_int")
parameter "d_20_int" = 42 (= "d_20 - 3.5 mm")
parameter "d_21" = 42 (= "d_20_int")
parameter "d_21_int" = 38.5 (= "d_21 - 3.5 mm")
parameter "h_21" = 210
parameter "h_22" = 220
parameter "h_23" = 295
parameter "h_24" = 295
parameter "h_25" = 300
parameter "h_26" = 290
parameter "h_27" = 305
parameter "h_28" = 285
parameter "d_22" = 38.5 (= "d_21_int")
parameter "d_22_int" = 35 (= "d_22 - 3.5 mm")
parameter "d_23" = 35 (= "d_22_int")
parameter "d_23_int" = 31.5 (= "d_23 - 3.5 mm")
parameter "d_24" = 31.5 (= "d_23_int")
parameter "d_24_int" = 28 (= "d_24 - 3.5 mm")
parameter "d_25" = 28 (= "d_24_int")
parameter "d_25_int" = 24.5 (= "d_25 - 3.5 mm")
parameter "d_26" = 24.5 (= "d_25_int")
parameter "d_26_int" = 21 (= "d_26 - 3.5 mm")
parameter "d_27" = 21 (= "d_26_int")
parameter "d_27_int" = 17.5 (= "d_27 - 3.5 mm")
parameter "d_28" = 17.5 (= "d_27_int")
parameter "d_28_int" = 14 (= "d_28 - 3.5 mm")
parameter "d_29" = 14 (= "d_28_int")
parameter "d_29_int" = 10.5 (= "d_29 - 3.5 mm")
sketch "Boceto1" plane through (0, 0, 0) normal (0, 1, 0) x axis (1, 0, 0)
  circle C1 centre (0, 0) radius 56
  circle C2 centre (0, 0) radius 54.25
  point P1 (0, 0)
  point P2 (0, 0)
  coincident P1 P2
  concentric C1 C2
  dimension "d1" diameter C1 = 112 (= "d_1")
  dimension "d2" diameter C2 = 108.5 (= "d_1_int")
extrude "Extruir1" new body sketch "Boceto1" along normal blind 3
work_plane "PlanoDeObra2" AlongDistance -10 (= "h_1")
sketch "Boceto3" plane through (0, -10, 0) normal (0, 1, 0) x axis (1, 0, 0)
  circle C1 centre (0, 0) radius 54.25
  circle C2 centre (0, 0) radius 52.5
  point P1 (0, 0)
  point P2 (0, 0)
  coincident P1 P2
  concentric C1 C2
  dimension "d12" diameter C2 = 105 (= "d_2_int")
  dimension "d13" diameter C1 = 108.5 (= "d_2")
extrude "Extruir2" new body sketch "Boceto3" along normal blind 3
work_plane "PlanoDeObra3" AlongDistance 0
work_plane "PlanoDeObra4" AlongDistance 10 (= "h_2")
sketch "Boceto4" plane through (0, 10, 0) normal (0, 1, 0) x axis (1, 0, 0)
  circle C1 centre (0, 0) radius 52.5
  circle C2 centre (0, 0) radius 50.75
  point P1 (0, 0)
  point P2 (0, 0)
  point P3 (0, 0)
  coincident P1 P2
  coincident P1 P3
  dimension "d26" diameter C1 = 105 (= "d_3")
  dimension "d27" diameter C2 = 101.5 (= "d_3_int")
extrude "Extruir3" new body sketch "Boceto4" along normal blind 3
work_plane "PlanoDeObra5" AlongDistance -20 (= "h_3")
sketch "Boceto5" plane through (0, -20, 0) normal (0, 1, 0) x axis (1, 0, 0)
  circle C1 centre (0, 0) radius 50.75
  circle C2 centre (0, 0) radius 49
  point P1 (0, 0)
  point P2 (0, 0)
  point P3 (0, 0)
  coincident P1 P2
  coincident P1 P3
  dimension "d41" diameter C1 = 101.5 (= "d_4")
  dimension "d42" diameter C2 = 98 (= "d_4_int")
extrude "Extruir4" new body sketch "Boceto5" along normal blind 3
work_plane "PlanoDeObra6" AlongDistance 20 (= "h_4")
sketch "Boceto6" plane through (0, 20, 0) normal (0, 1, 0) x axis (1, 0, 0)
  circle C1 centre (0, 0) radius 49
  circle C2 centre (0, 0) radius 47.25
  point P1 (0, 0)
  point P2 (0, 0)
  coincident P1 P2
  concentric C1 C2
  dimension "d46" diameter C1 = 98 (= "d_5")
  dimension "d47" diameter C2 = 94.5 (= "d_5_int")
extrude "Extruir5" new body sketch "Boceto6" along normal blind 3
work_plane "PlanoDeObra7" AlongDistance -30 (= "h_5")
sketch "Boceto7" plane through (0, -30, 0) normal (0, 1, 0) x axis (1, 0, 0)
  circle C1 centre (0, 0) radius 47.25
  circle C2 centre (0, 0) radius 45.5
  point P1 (0, 0)
  point P2 (0, 0)
  coincident P1 P2
  concentric C1 C2
  dimension "d51" diameter C1 = 94.5 (= "d_6")
  dimension "d52" diameter C2 = 91 (= "d_6_int")
extrude "Extruir6" new body sketch "Boceto7" along normal blind 3
work_plane "PlanoDeObra8" AlongDistance 30 (= "h_6")
sketch "Boceto9" plane through (0, 30, 0) normal (0, 1, 0) x axis (1, 0, 0)
  circle C1 centre (0, 0) radius 45.5
  circle C2 centre (0, 0) radius 43.75
  point P1 (0, 0)
  point P2 (0, 0)
  point P3 (0, 0)
  coincident P1 P2
  coincident P1 P3
  dimension "d56" diameter C1 = 91 (= "d_7")
  dimension "d57" diameter C2 = 87.5 (= "d_7_int")
extrude "Extruir7" new body sketch "Boceto9" along normal blind 3
work_plane "PlanoDeObra9" AlongDistance 40 (= "h_7")
sketch "Boceto10" plane through (0, 40, 0) normal (0, 1, 0) x axis (1, 0, 0)
  circle C1 centre (0, 0) radius 43.75
  circle C2 centre (0, 0) radius 42
  point P1 (0, 0)
  point P2 (0, 0)
  coincident P1 P2
  concentric C1 C2
  dimension "d61" diameter C1 = 87.5 (= "d_8")
  dimension "d62" diameter C2 = 84 (= "d_8_int")
extrude "Extruir8" new body sketch "Boceto10" along normal blind 3
work_plane "PlanoDeObra10" AlongDistance 50 (= "h_8")
sketch "Boceto11" plane through (0, 50, 0) normal (0, 1, 0) x axis (1, 0, 0)
  circle C1 centre (0, 0) radius 42
  circle C2 centre (0, 0) radius 40.25
  point P1 (0, 0)
  point P2 (0, 0)
  coincident P1 P2
  concentric C1 C2
  dimension "d90" diameter C1 = 84 (= "d_9")
  dimension "d91" diameter C2 = 80.5 (= "d_9_int")
extrude "Extruir9" new body sketch "Boceto11" along normal blind 3
work_plane "PlanoDeObra11" AlongDistance 60 (= "h_9")
sketch "Boceto12" plane through (0, 60, 0) normal (0, 1, 0) x axis (1, 0, 0)
  circle C1 centre (0, 0) radius 40.25
  circle C2 centre (0, 0) radius 38.5
  point P1 (0, 0)
  point P2 (0, 0)
  point P3 (0, 0)
  coincident P1 P2
  coincident P1 P3
  dimension "d95" diameter C1 = 80.5 (= "d_10")
  dimension "d96" diameter C2 = 77 (= "d_10_int")
extrude "Extruir10" new body sketch "Boceto12" along normal blind 3
work_plane "PlanoDeObra12" AlongDistance 70 (= "h_10")
sketch "Boceto13" plane through (0, 70, 0) normal (0, 1, 0) x axis (1, 0, 0)
  circle C1 centre (0, 0) radius 38.5
  circle C2 centre (0, 0) radius 36.75
  point P1 (0, 0)
  point P2 (0, 0)
  point P3 (0, 0)
  coincident P1 P2
  coincident P1 P3
  dimension "d100" diameter C1 = 77 (= "d_11")
  dimension "d101" diameter C2 = 73.5 (= "d_11_int")
extrude "Extruir11" new body sketch "Boceto13" along normal blind 3
work_plane "PlanoDeObra13" AlongDistance 110 (= "h_11")
sketch "Boceto14" plane through (0, 110, 0) normal (0, 1, 0) x axis (1, 0, 0)
  circle C1 centre (0, 0) radius 36.75
  circle C2 centre (0, 0) radius 35
  point P1 (0, 0)
  point P2 (0, 0)
  coincident P1 P2
  concentric C1 C2
  dimension "d105" diameter C1 = 73.5 (= "d_12")
  dimension "d106" diameter C2 = 70 (= "d_12_int")
work_plane "PlanoDeObra14" AlongDistance 120 (= "h_12")
sketch "Boceto15" plane through (0, 120, 0) normal (0, 1, 0) x axis (1, 0, 0)
  circle C1 centre (0, 0) radius 35
  circle C2 centre (0, 0) radius 33.25
  point P1 (0, 0)
  point P2 (0, 0)
  coincident P1 P2
  concentric C1 C2
  dimension "d110" diameter C1 = 70 (= "d_13")
  dimension "d111" diameter C2 = 66.5 (= "d_13_int")
work_plane "PlanoDeObra15" AlongDistance 130 (= "h_13")
sketch "Boceto16" plane through (0, 130, 0) normal (0, 1, 0) x axis (1, 0, 0)
  circle C1 centre (0, 0) radius 33.25
  circle C2 centre (0, 0) radius 31.5
  point P1 (0, 0)
  point P2 (0, 0)
  coincident P1 P2
  concentric C1 C2
  dimension "d115" diameter C1 = 66.5 (= "d_14")
  dimension "d116" diameter C2 = 63 (= "d_14_int")
work_plane "PlanoDeObra17" AlongDistance 140 (= "h_14")
sketch "Boceto17" plane through (0, 140, 0) normal (0, 1, 0) x axis (1, 0, 0)
  circle C1 centre (0, 0) radius 31.5
  circle C2 centre (0, 0) radius 29.75
  point P1 (0, 0)
  point P2 (0, 0)
  point P3 (0, 0)
  coincident P1 P2
  coincident P1 P3
  dimension "d121" diameter C1 = 63 (= "d_15")
  dimension "d122" diameter C2 = 59.5 (= "d_15_int")
work_plane "PlanoDeObra18" AlongDistance 80 (= "h_15")
sketch "Boceto18" plane through (0, 80, 0) normal (0, 1, 0) x axis (1, 0, 0)
  circle C1 centre (0, 0) radius 29.75
  circle C2 centre (0, 0) radius 28
  point P1 (0, 0)
  point P2 (0, 0)
  point P3 (0, 0)
  coincident P1 P2
  coincident P1 P3
  dimension "d126" diameter C1 = 59.5 (= "d_16")
  dimension "d127" diameter C2 = 56 (= "d_16_int")
extrude "Extruir16" new body sketch "Boceto18" along normal blind 3
work_plane "PlanoDeObra19" AlongDistance 160 (= "h_16")
sketch "Boceto19" plane through (0, 160, 0) normal (0, 1, 0) x axis (1, 0, 0)
  circle C1 centre (0, 0) radius 28
  circle C2 centre (0, 0) radius 26.25
  point P1 (0, 0)
  point P2 (0, 0)
  coincident P1 P2
  concentric C1 C2
  dimension "d162" diameter C1 = 56 (= "d_17")
  dimension "d163" diameter C2 = 52.5 (= "d_17_int")
work_plane "PlanoDeObra20" AlongDistance 170 (= "h_17")
sketch "Boceto20" plane through (0, 170, 0) normal (0, 1, 0) x axis (1, 0, 0)
  circle C1 centre (0, 0) radius 26.25
  circle C2 centre (0, 0) radius 24.5
  point P1 (0, 0)
  point P2 (0, 0)
  coincident P1 P2
  concentric C1 C2
  dimension "d167" diameter C1 = 52.5 (= "d_18")
  dimension "d168" diameter C2 = 49 (= "d_18_int")
work_plane "PlanoDeObra21" AlongDistance 180 (= "h_18")
sketch "Boceto21" plane through (0, 180, 0) normal (0, 1, 0) x axis (1, 0, 0)
  circle C1 centre (0, 0) radius 24.5
  circle C2 centre (0, 0) radius 22.75
  point P1 (0, 0)
  point P2 (0, 0)
  point P3 (0, 0)
  coincident P1 P2
  coincident P1 P3
  dimension "d172" diameter C1 = 49 (= "d_19")
  dimension "d173" diameter C2 = 45.5 (= "d_19_int")
work_plane "PlanoDeObra22" AlongDistance 90 (= "h_19")
sketch "Boceto22" plane through (0, 90, 0) normal (0, 1, 0) x axis (1, 0, 0)
  circle C1 centre (0, 0) radius 22.75
  circle C2 centre (0, 0) radius 21
  point P1 (0, 0)
  point P2 (0, 0)
  point P3 (0, 0)
  coincident P1 P2
  coincident P1 P3
  dimension "d177" diameter C1 = 45.5 (= "d_20")
  dimension "d178" diameter C2 = 42 (= "d_20_int")
extrude "Extruir20" new body sketch "Boceto22" along normal blind 3
work_plane "PlanoDeObra24" AlongDistance 200 (= "h_20")
sketch "Boceto24" plane through (0, 200, 0) normal (0, 1, 0) x axis (1, 0, 0)
  circle C1 centre (0, 0) radius 21
  circle C2 centre (0, 0) radius 19.25
  point P1 (0, 0)
  point P2 (0, 0)
  point P3 (0, 0)
  coincident P1 P2
  coincident P1 P3
  dimension "d187" diameter C1 = 42 (= "d_21")
  dimension "d188" diameter C2 = 38.5 (= "d_21_int")
work_plane "PlanoDeObra25" AlongDistance 210 (= "h_21")
sketch "Boceto25" plane through (0, 210, 0) normal (0, 1, 0) x axis (1, 0, 0)
  circle C1 centre (0, 0) radius 19.25
  circle C2 centre (0, 0) radius 17.5
  point P1 (0, 0)
  point P2 (0, 0)
  coincident P1 P2
  concentric C1 C2
  dimension "d220" diameter C1 = 38.5 (= "d_22")
  dimension "d221" diameter C2 = 35 (= "d_22_int")
work_plane "PlanoDeObra26" AlongDistance 220 (= "h_22")
sketch "Boceto26" plane through (0, 220, 0) normal (0, 1, 0) x axis (1, 0, 0)
  circle C1 centre (0, 0) radius 17.5
  circle C2 centre (0, 0) radius 15.75
  point P1 (0, 0)
  point P2 (0, 0)
  coincident P1 P2
  concentric C1 C2
  dimension "d225" diameter C1 = 35 (= "d_23")
  dimension "d226" diameter C2 = 31.5 (= "d_23_int")
work_plane "PlanoDeObra28" AlongDistance 295 (= "h_23")
sketch "Boceto27" plane through (0, 295, 0) normal (0, 1, 0) x axis (1, 0, 0)
  circle C1 centre (0, 0) radius 15.75
  circle C2 centre (0, 0) radius 14
  point P1 (0, 0)
  point P2 (0, 0)
  coincident P1 P2
  concentric C1 C2
  dimension "d231" diameter C1 = 31.5 (= "d_24")
  dimension "d232" diameter C2 = 28 (= "d_24_int")
work_plane "PlanoDeObra29" AlongDistance 295 (= "h_24")
sketch "Boceto28" plane through (0, 295, 0) normal (0, 1, 0) x axis (1, 0, 0)
  circle C1 centre (0, 0) radius 14
  circle C2 centre (0, 0) radius 12.25
  point P1 (0, 0)
  point P2 (0, 0)
  point P3 (0, 0)
  coincident P1 P2
  coincident P1 P3
  dimension "d236" diameter C1 = 28 (= "d_25")
  dimension "d237" diameter C2 = 24.5 (= "d_25_int")
work_plane "PlanoDeObra30" AlongDistance 300 (= "h_25")
sketch "Boceto29" plane through (0, 300, 0) normal (0, 1, 0) x axis (1, 0, 0)
  circle C1 centre (0, 0) radius 12.25
  circle C2 centre (0, 0) radius 10.5
  point P1 (0, 0)
  point P2 (0, 0)
  coincident P1 P2
  concentric C1 C2
  dimension "d241" diameter C1 = 24.5 (= "d_26")
  dimension "d242" diameter C2 = 21 (= "d_26_int")
work_plane "PlanoDeObra31" AlongDistance 290 (= "h_26")
sketch "Boceto30" plane through (0, 290, 0) normal (0, 1, 0) x axis (1, 0, 0)
  circle C1 centre (0, 0) radius 10.5
  circle C2 centre (0, 0) radius 8.75
  point P1 (0, 0)
  point P2 (0, 0)
  point P3 (0, 0)
  coincident P1 P2
  coincident P1 P3
  dimension "d246" diameter C1 = 21 (= "d_27")
  dimension "d247" diameter C2 = 17.5 (= "d_27_int")
work_plane "PlanoDeObra32" AlongDistance 305 (= "h_27")
sketch "Boceto31" plane through (0, 305, 0) normal (0, 1, 0) x axis (1, 0, 0)
  circle C1 centre (0, 0) radius 8.75
  circle C2 centre (0, 0) radius 7
  point P1 (0, 0)
  point P2 (0, 0)
  coincident P1 P2
  concentric C1 C2
  dimension "d251" diameter C1 = 17.5 (= "d_28")
  dimension "d252" diameter C2 = 14 (= "d_28_int")
work_plane "PlanoDeObra33" AlongDistance 285 (= "h_28")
